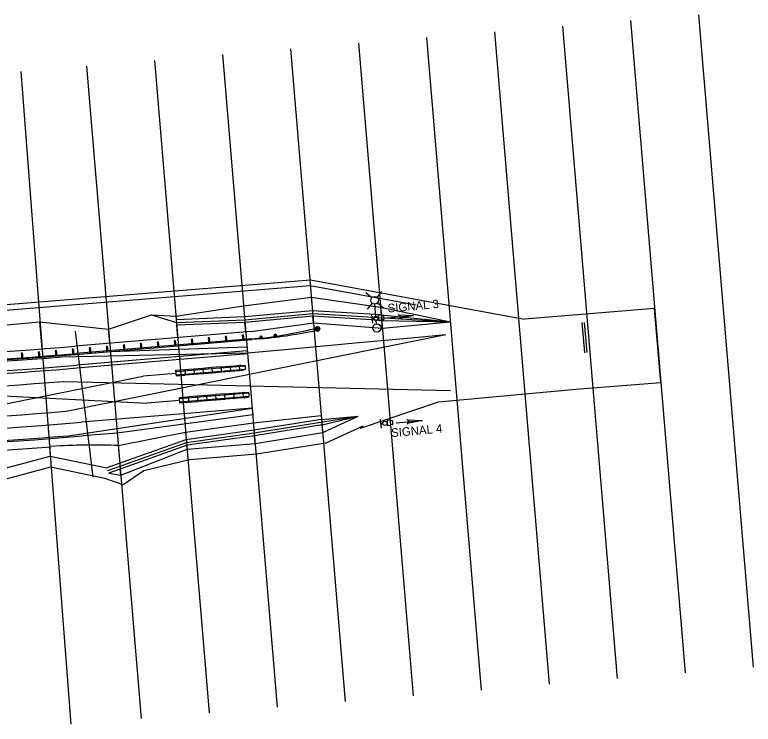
# Model space of a CAD drawing. Extents: x 223098 to 226975, y 386666 to 387582.
# Drawn here: x 223996.7 to 224267.2, y 387146.4 to 387406.5 of the extents above; entities that cross this region are included whole.
import ezdxf

# ---------------------------------------------------------------- set-up
doc = ezdxf.new("R2010")
doc.units = 0
for name, color, linetype in [('BD_X_Building', 7, 'Continuous'), ('Default', 7, 'Continuous'), ('DR_X_Erosion_Control', 7, 'Continuous'), ('DR_X_Headwall', 7, 'Continuous'), ('PF_X_Ground_Line', 7, 'Continuous'), ('PV_X_Driveway', 7, 'Continuous'), ('PV_X_EOP', 7, 'Continuous'), ('RW_X_CL_100_Distances', 7, 'Continuous'), ('RW_X_CL_100_Stations', 7, 'Continuous'), ('SV_X_Toe_of_Slope', 7, 'Continuous'), ('UT_X_Gas', 7, 'Continuous'), ('UT_X_Gas_Cells', 7, 'Continuous'), ('UT_X_Water_Cells', 7, 'Continuous'), ('VG_X_Cells', 7, 'Continuous')]:
    doc.layers.add(name, color=color, linetype=linetype)

msp = doc.modelspace()

# ---------------------------------------------------------------- linework, layer by layer
at = {"layer": 'BD_X_Building'}
for p, q in [((223981.08, 387297.25), (224104.98, 387307.24)), ((224104.98, 387307.24), (224143.7, 387300.16))]:
    msp.add_line(p, q, dxfattribs=at)
at = {"layer": 'Default'}
for p, q in [((224247.19, 387406.47), (224267.23, 387167.3)), ((224222.28, 387404.38), (224242.32, 387165.22)), ((224197.36, 387402.29), (224217.4, 387163.13)), ((224147.54, 387398.11), (224167.58, 387158.95)), ((224172.45, 387400.2), (224192.49, 387161.04)), ((224122.62, 387396.03), (224142.67, 387156.87)), ((224097.71, 387393.94), (224117.75, 387154.78)), ((224047.89, 387389.76), (224067.93, 387150.6)), ((224072.8, 387391.85), (224092.84, 387152.69)), ((224022.97, 387387.68), (224043.01, 387148.52)), ((223998.9, 387385.7), (224017.26, 387146.4))]:
    msp.add_line(p, q, dxfattribs=at)
at = {"layer": 'DR_X_Erosion_Control'}
for points in [[(223784.61, 387295.04), (223809.49, 387297.84), (223882.41, 387297.94), (223901.62, 387311.13), (223956.35, 387312.9), (223981.51, 387299.29), (224105.08, 387309.26), (224183.43, 387294.86)], [(224123.41, 387254.93), (224151.94, 387264.54), (224202.29, 387269.2), (224233.4, 387271.67), (224231.12, 387298.85), (224183.43, 387294.86)], [(224124.2, 387255.62), (224110.66, 387249.46), (224085.23, 387245.34), (224060.74, 387243.36)], [(224060.74, 387243.36), (224043.93, 387239.28), (224036.37, 387234.1), (224029.67, 387236.44)], [(224029.67, 387236.44), (224009.82, 387240.6), (223986.06, 387234.3), (223961.4, 387224.07)]]:
    msp.add_lwpolyline(points, dxfattribs=at)
at = {"layer": 'DR_X_Headwall'}
for points in [[(224046.84, 387296.42), (224055.94, 387293.66), (224080.94, 387294.69), (224105.84, 387296.97), (224156.27, 387293.86)], [(224030.83, 387239.41), (224059.62, 387249.72), (224084.42, 387253.17), (224122.54, 387259.27)]]:
    msp.add_lwpolyline(points, dxfattribs=at)
at = {"layer": 'PF_X_Ground_Line'}
for p, q in [((224013.89, 387281.05), (224081.96, 387282.5)), ((224014.62, 387272.08), (224156.38, 387268.68)), ((223973.16, 387267.73), (224045.07, 387264.09)), ((224056.97, 387265.76), (224082.37, 387267.89)), ((224073.72, 387267.49), (224076.71, 387267.75)), ((224076.71, 387267.75), (224076.89, 387267.59)), ((224076.89, 387267.59), (224077.04, 387267.77)), ((224077.04, 387267.77), (224080.03, 387268.02)), ((224080.03, 387268.02), (224080.21, 387267.87)), ((224080.21, 387267.87), (224080.36, 387268.05)), ((224080.21, 387267.87), (224080.35, 387266.21)), ((224080.36, 387268.05), (224080.8, 387268.09)), ((224080.8, 387268.09), (224082.31, 387267.96)), ((224057.03, 387265.09), (224045.07, 387264.09)), ((224060.1, 387266.35), (224056.94, 387266.09)), ((224056.94, 387266.09), (224057.11, 387264.1)), ((224082.48, 387266.56), (224057.08, 387264.43)), ((224060.1, 387266.35), (224060.28, 387266.2)), ((224060.28, 387266.2), (224060.43, 387266.38)), ((224060.28, 387266.2), (224060.42, 387264.54)), ((224063.42, 387266.63), (224060.43, 387266.38)), ((224063.42, 387266.63), (224063.6, 387266.48)), ((224063.6, 387266.48), (224063.75, 387266.66)), ((224063.6, 387266.48), (224063.74, 387264.82)), ((224066.74, 387266.91), (224063.75, 387266.66)), ((224066.74, 387266.91), (224066.92, 387266.76)), ((224066.91, 387264.92), (224067.06, 387265.1)), ((224066.92, 387266.76), (224067.08, 387266.94)), ((224066.92, 387266.76), (224067.06, 387265.1)), ((224067.06, 387265.1), (224067.24, 387264.94)), ((224070.06, 387267.19), (224067.08, 387266.94)), ((224070.23, 387265.2), (224067.24, 387264.94)), ((224070.06, 387267.19), (224070.24, 387267.04)), ((224070.23, 387265.2), (224070.38, 387265.38)), ((224070.24, 387267.04), (224070.4, 387267.22)), ((224070.24, 387267.04), (224070.38, 387265.38)), ((224070.38, 387265.38), (224070.56, 387265.22)), ((224073.39, 387267.47), (224070.4, 387267.22)), ((224073.55, 387265.47), (224070.56, 387265.22)), ((224073.39, 387267.47), (224073.57, 387267.31)), ((224073.55, 387265.47), (224073.71, 387265.65)), ((224073.57, 387267.31), (224073.72, 387267.49)), ((224073.57, 387267.31), (224073.71, 387265.65)), ((224073.71, 387265.65), (224073.89, 387265.5)), ((224076.87, 387265.75), (224073.89, 387265.5)), ((224076.87, 387265.75), (224077.03, 387265.93)), ((224076.89, 387267.59), (224077.03, 387265.93)), ((224077.03, 387265.93), (224077.21, 387265.78)), ((224080.2, 387266.03), (224077.21, 387265.78)), ((224080.2, 387266.03), (224080.35, 387266.21)), ((224080.35, 387266.21), (224080.53, 387266.06)), ((224080.96, 387266.09), (224080.53, 387266.06)), ((224080.96, 387266.09), (224082.44, 387266.47)), ((224060.27, 387264.36), (224057.11, 387264.1)), ((224060.27, 387264.36), (224060.42, 387264.54)), ((224060.42, 387264.54), (224060.6, 387264.39)), ((224063.59, 387264.64), (224060.6, 387264.39)), ((224063.59, 387264.64), (224063.74, 387264.82)), ((224063.74, 387264.82), (224063.92, 387264.67)), ((224066.91, 387264.92), (224063.92, 387264.67))]:
    msp.add_line(p, q, dxfattribs=at)
msp.add_lwpolyline([(224081.96, 387282.5), (224095.64, 387283.79), (224120.18, 387286.09), (224144.5, 387288.28), (224154.66, 387289.21)], dxfattribs=at)
for centre, radius, start, end in [((223874.12, 389011.68), 1736.26, 268.92281, 274.61725), ((223874.12, 389011.68), 1745.26, 268.92281, 274.61725), ((224081.27, 387267.12), 1.34, 330.6142, 38.9656)]:
    msp.add_arc(centre, radius, start, end, dxfattribs=at)
at = {"layer": 'PV_X_Driveway'}
for p, q in [((224107.52, 387291.71), (224107.7, 387290.86)), ((224083.54, 387287.67), (224019.04, 387282.26)), ((224019.06, 387281.98), (224083.56, 387287.39)), ((224061.99, 387285.86), (224061.41, 387286.82)), ((224061.49, 387285.82), (224061.9, 387286.86)), ((224068.22, 387286.38), (224067.63, 387287.34)), ((224067.72, 387286.34), (224068.13, 387287.38)), ((224074.44, 387286.9), (224073.86, 387287.86)), ((224073.95, 387286.86), (224074.36, 387287.9)), ((224080.67, 387287.43), (224080.09, 387288.38)), ((224080.17, 387287.38), (224080.59, 387288.42)), ((224086.95, 387287.67), (224083.56, 387287.39)), ((224086.93, 387287.89), (224083.68, 387287.61)), ((224030.85, 387283.25), (224030.27, 387284.21)), ((224030.35, 387283.21), (224030.76, 387284.25)), ((224037.08, 387283.77), (224036.49, 387284.73)), ((224036.58, 387283.73), (224036.99, 387284.77)), ((224043.3, 387284.29), (224042.72, 387285.25)), ((224042.81, 387284.25), (224043.22, 387285.29)), ((224049.53, 387284.82), (224048.95, 387285.77)), ((224049.03, 387284.78), (224049.45, 387285.81)), ((224055.76, 387285.34), (224055.18, 387286.29)), ((224055.26, 387285.3), (224055.68, 387286.34)), ((223999.7, 387280.75), (223999.13, 387281.71)), ((223999.2, 387280.71), (223999.63, 387281.75)), ((224005.93, 387281.21), (224005.36, 387282.17)), ((224005.43, 387281.18), (224005.86, 387282.21)), ((224012.16, 387281.7), (224011.59, 387282.66)), ((224011.66, 387281.66), (224012.08, 387282.7)), ((224018.39, 387282.21), (224017.81, 387283.16)), ((224017.89, 387282.17), (224018.31, 387283.2)), ((224024.62, 387282.73), (224024.04, 387283.68)), ((224024.12, 387282.69), (224024.54, 387283.73))]:
    msp.add_line(p, q, dxfattribs=at)
for points in [[(224108.4, 387291.06), (224107.28, 387292.08)], [(224108.36, 387291.65), (224107.88, 387292.1)], [(224092.53, 387288.85), (224091.97, 387289.36)], [(224092.51, 387289.15), (224092.27, 387289.37)], [(224107.78, 387290.5), (224106.78, 387291.41)], [(224108.17, 387290.7), (224106.95, 387291.82)], [(224087.04, 387287.9), (224086.54, 387288.35)], [(224087.24, 387288), (224086.63, 387288.56)], [(224087.35, 387288.18), (224086.79, 387288.69)], [(224087.34, 387288.48), (224087.09, 387288.7)], [(224092.22, 387288.57), (224091.72, 387289.03)], [(224092.42, 387288.67), (224091.81, 387289.23)]]:
    msp.add_lwpolyline(points, dxfattribs=at)
for points in [[(224055.62, 387287), (224055.12, 387286.96), (224055.18, 387286.29), (224055.68, 387286.34)], [(224061.85, 387287.52), (224061.35, 387287.48), (224061.41, 387286.82), (224061.9, 387286.86)], [(224061.9, 387286.86), (224061.41, 387286.82), (224061.49, 387285.82), (224061.99, 387285.86)], [(224068.08, 387288.04), (224067.58, 387288), (224067.63, 387287.34), (224068.13, 387287.38)], [(224068.13, 387287.38), (224067.63, 387287.34), (224067.72, 387286.34), (224068.22, 387286.38)], [(224074.31, 387288.57), (224073.81, 387288.52), (224073.86, 387287.86), (224074.36, 387287.9)], [(224074.36, 387287.9), (224073.86, 387287.86), (224073.95, 387286.86), (224074.44, 387286.9)], [(224080.53, 387289.09), (224080.04, 387289.05), (224080.09, 387288.38), (224080.59, 387288.42)], [(224080.59, 387288.42), (224080.09, 387288.38), (224080.17, 387287.38), (224080.67, 387287.43)], [(224024.48, 387284.39), (224023.98, 387284.35), (224024.04, 387283.68), (224024.54, 387283.73)], [(224030.71, 387284.91), (224030.21, 387284.87), (224030.27, 387284.21), (224030.76, 387284.25)], [(224030.76, 387284.25), (224030.27, 387284.21), (224030.35, 387283.21), (224030.85, 387283.25)], [(224036.94, 387285.43), (224036.44, 387285.39), (224036.49, 387284.73), (224036.99, 387284.77)], [(224036.99, 387284.77), (224036.49, 387284.73), (224036.58, 387283.73), (224037.08, 387283.77)], [(224043.16, 387285.96), (224042.67, 387285.91), (224042.72, 387285.25), (224043.22, 387285.29)], [(224043.22, 387285.29), (224042.72, 387285.25), (224042.81, 387284.25), (224043.3, 387284.29)], [(224049.39, 387286.48), (224048.89, 387286.44), (224048.95, 387285.77), (224049.45, 387285.81)], [(224049.45, 387285.81), (224048.95, 387285.77), (224049.03, 387284.78), (224049.53, 387284.82)], [(224055.68, 387286.34), (224055.18, 387286.29), (224055.26, 387285.3), (224055.76, 387285.34)], [(223999.58, 387282.41), (223999.08, 387282.38), (223999.13, 387281.71), (223999.63, 387281.75)], [(223999.63, 387281.75), (223999.13, 387281.71), (223999.2, 387280.71), (223999.7, 387280.75)], [(224005.81, 387282.88), (224005.31, 387282.84), (224005.36, 387282.17), (224005.86, 387282.21)], [(224005.86, 387282.21), (224005.36, 387282.17), (224005.43, 387281.18), (224005.93, 387281.21)], [(224012.03, 387283.36), (224011.53, 387283.32), (224011.59, 387282.66), (224012.08, 387282.7)], [(224012.08, 387282.7), (224011.59, 387282.66), (224011.66, 387281.66), (224012.16, 387281.7)], [(224018.25, 387283.87), (224017.75, 387283.83), (224017.81, 387283.16), (224018.31, 387283.2)], [(224018.31, 387283.2), (224017.81, 387283.16), (224017.89, 387282.17), (224018.39, 387282.21)], [(224024.54, 387283.73), (224024.04, 387283.68), (224024.12, 387282.69), (224024.62, 387282.73)]]:
    msp.add_lwpolyline(points, close=True, dxfattribs=at)
for centre, radius in [((224107.61, 387291.31), 0.833), ((224092.14, 387288.98), 0.417), ((224086.96, 387288.31), 0.417)]:
    msp.add_circle(centre, radius, dxfattribs=at)
for centre, radius, start, end in [((224068.52, 387444.42), 157.61, 276.7092, 284.3274), ((224062.58, 387515.48), 229.11, 276.1069, 281.3587), ((223874.12, 389011.68), 1735.48, 269.08669, 274.7899), ((223874.12, 389011.68), 1735.76, 269.08671, 274.7899)]:
    msp.add_arc(centre, radius, start, end, dxfattribs=at)
at = {"layer": 'PV_X_EOP'}
for p, q in [((224204.46, 387293.61), (224205.39, 387282.54)), ((224206.39, 387282.63), (224205.46, 387293.69))]:
    msp.add_line(p, q, dxfattribs=at)
at = {"layer": 'RW_X_CL_100_Distances'}
for p, q in [((224015.5, 387261.12), (224154.66, 387289.21)), ((224058.77, 387276.28), (224055.62, 387276.01)), ((224055.62, 387276.01), (224055.78, 387274.02)), ((224055.64, 387275.68), (224081.04, 387277.81)), ((224081.16, 387276.48), (224055.76, 387274.35)), ((224058.77, 387276.28), (224058.95, 387276.13)), ((224058.95, 387276.13), (224059.1, 387276.31)), ((224058.95, 387276.13), (224059.09, 387274.46)), ((224062.09, 387276.56), (224059.1, 387276.31)), ((224062.09, 387276.56), (224062.27, 387276.4)), ((224062.27, 387276.4), (224062.43, 387276.58)), ((224062.27, 387276.4), (224062.41, 387274.74)), ((224065.42, 387276.83), (224062.43, 387276.58)), ((224065.42, 387276.83), (224065.6, 387276.68)), ((224065.6, 387276.68), (224065.75, 387276.86)), ((224065.6, 387276.68), (224065.74, 387275.02)), ((224068.74, 387277.11), (224065.75, 387276.86)), ((224068.74, 387277.11), (224068.92, 387276.96)), ((224068.92, 387276.96), (224069.07, 387277.14)), ((224068.92, 387276.96), (224069.06, 387275.3)), ((224072.06, 387277.39), (224069.07, 387277.14)), ((224072.06, 387277.39), (224072.24, 387277.24)), ((224072.24, 387277.24), (224072.39, 387277.42)), ((224072.24, 387277.24), (224072.38, 387275.58)), ((224072.39, 387277.42), (224075.38, 387277.67)), ((224075.38, 387277.67), (224075.56, 387277.52)), ((224075.55, 387275.68), (224075.7, 387275.86)), ((224075.56, 387277.52), (224075.71, 387277.7)), ((224075.56, 387277.52), (224075.7, 387275.86)), ((224075.7, 387275.86), (224075.88, 387275.7)), ((224075.71, 387277.7), (224078.7, 387277.95)), ((224078.87, 387275.95), (224075.88, 387275.7)), ((224078.7, 387277.95), (224078.88, 387277.8)), ((224078.87, 387275.95), (224079.02, 387276.13)), ((224078.88, 387277.8), (224079.03, 387277.98)), ((224078.88, 387277.8), (224079.02, 387276.13)), ((224079.02, 387276.13), (224079.2, 387275.98)), ((224079.03, 387277.98), (224079.47, 387278.01)), ((224079.64, 387276.02), (224079.2, 387275.98)), ((224079.47, 387278.01), (224080.99, 387277.89)), ((224079.64, 387276.02), (224081.11, 387276.39)), ((223973.18, 387259.72), (224043.74, 387274.01)), ((224055.7, 387275.02), (224043.74, 387274.01)), ((224058.94, 387274.28), (224055.78, 387274.02)), ((224058.94, 387274.28), (224059.09, 387274.46)), ((224059.09, 387274.46), (224059.27, 387274.31)), ((224062.26, 387274.56), (224059.27, 387274.31)), ((224062.26, 387274.56), (224062.41, 387274.74)), ((224062.41, 387274.74), (224062.59, 387274.59)), ((224065.58, 387274.84), (224062.59, 387274.59)), ((224065.58, 387274.84), (224065.74, 387275.02)), ((224065.74, 387275.02), (224065.92, 387274.87)), ((224068.9, 387275.12), (224065.92, 387274.87)), ((224068.9, 387275.12), (224069.06, 387275.3)), ((224069.06, 387275.3), (224069.24, 387275.15)), ((224072.23, 387275.4), (224069.24, 387275.15)), ((224072.23, 387275.4), (224072.38, 387275.58)), ((224072.38, 387275.58), (224072.56, 387275.43)), ((224075.55, 387275.68), (224072.56, 387275.43)), ((224016.23, 387252.15), (224083.66, 387262.22))]:
    msp.add_line(p, q, dxfattribs=at)
for centre, radius, start, end in [((224079.95, 387277.05), 1.34, 330.6142, 38.9656), ((223874.12, 389011.68), 1756.26, 268.92281, 274.61725), ((223874.12, 389011.68), 1765.26, 268.92281, 274.61725)]:
    msp.add_arc(centre, radius, start, end, dxfattribs=at)
at = {"layer": 'RW_X_CL_100_Stations'}
for p, q in [((224127.45, 387302.68), (224125.31, 387304.49)), ((224129.42, 387302.84), (224131.23, 387304.98)), ((224127.62, 387300.71), (224125.8, 387298.57)), ((224129.01, 387295.9), (224128.63, 387300.38)), ((224129.59, 387300.87), (224131.73, 387299.06)), ((224127.82, 387293.41), (224127.52, 387296.63)), ((224127.66, 387295.14), (224128.32, 387295.2)), ((224127.68, 387294.9), (224128.34, 387294.96)), ((224129.8, 387295.34), (224130.07, 387295.36)), ((224129.8, 387295.34), (224130.07, 387295.36)), ((224129.83, 387295.1), (224130.09, 387295.12)), ((224129.83, 387295.1), (224130.09, 387295.12)), ((224131.13, 387296.31), (224129.99, 387296.21)), ((224130.17, 387294.27), (224129.99, 387296.21)), ((224131.31, 387294.38), (224131.13, 387296.31)), ((224131.64, 387296.11), (224131.16, 387296.06)), ((224133.17, 387295.37), (224142.79, 387296.24)), ((224137.12, 387296.44), (224142.79, 387296.24)), ((224142.79, 387296.24), (224137.25, 387295.04)), ((224129.24, 387293.14), (224129.14, 387294.4)), ((224131.31, 387294.38), (224130.17, 387294.27)), ((224131.77, 387294.67), (224131.29, 387294.63)), ((224131.04, 387254.95), (224130.74, 387258.18)), ((224133.03, 387256.88), (224133.29, 387256.91)), ((224133.03, 387256.88), (224133.29, 387256.91)), ((224134.35, 387257.86), (224133.21, 387257.76)), ((224133.39, 387255.82), (224133.21, 387257.76)), ((224134.53, 387255.93), (224134.35, 387257.86)), ((224134.87, 387257.66), (224134.38, 387257.61)), ((224134.87, 387257.66), (224134.38, 387257.61)), ((224136.39, 387256.92), (224146.01, 387257.79)), ((224140.35, 387257.98), (224146.01, 387257.79)), ((224146.01, 387257.79), (224140.47, 387256.58)), ((224130.88, 387256.69), (224131.54, 387256.75)), ((224130.88, 387256.69), (224131.54, 387256.75)), ((224130.9, 387256.45), (224131.56, 387256.51)), ((224130.9, 387256.45), (224131.56, 387256.51)), ((224133.05, 387256.65), (224133.31, 387256.67)), ((224133.05, 387256.65), (224133.31, 387256.67)), ((224134.53, 387255.93), (224133.39, 387255.82)), ((224135, 387256.22), (224134.51, 387256.18)), ((224135, 387256.22), (224134.51, 387256.18))]:
    msp.add_line(p, q, dxfattribs=at)
for centre, radius in [((224128.52, 387301.78), 1.4), ((224129.07, 387295.15), 0.757), ((224129.37, 387291.65), 1.5), ((224132.29, 387256.7), 0.757)]:
    msp.add_circle(centre, radius, dxfattribs=at)
for centre in [(224137.19, 387295.74), (224140.41, 387257.28)]:
    msp.add_arc(centre, 0.702, 275.1298, 95.1298, dxfattribs=at)
for centre in [(224131.71, 387295.39), (224134.93, 387256.94), (224134.93, 387256.94)]:
    msp.add_ellipse(centre, major_axis=(0.066, -0.718), ratio=0.45371, start_param=0, end_param=3.141593, dxfattribs=at)
at = {"layer": 'SV_X_Toe_of_Slope'}
for p, q in [((224105.34, 387302.96), (224105.75, 387297.97)), ((224080.51, 387299.82), (224080.86, 387295.69)), ((224130.73, 387299.26), (224130.98, 387296.3)), ((224055.75, 387295.93), (224055.86, 387294.66)), ((224106.12, 387293.6), (224105.92, 387295.96)), ((224130.97, 387296.42), (224156.27, 387293.86)), ((224006.7, 387284), (224005.94, 387293.96)), ((224056.4, 387288.12), (224056.02, 387292.66)), ((224081.32, 387290.21), (224081.02, 387293.7)), ((224131.14, 387294.41), (224156.27, 387293.86)), ((224131.37, 387291.62), (224131.14, 387294.41)), ((224083.31, 387290.38), (224018.81, 387284.97)), ((224031.49, 387286.03), (224031.06, 387291.22)), ((224108.97, 387259.58), (224109.09, 387258.13)), ((224109.09, 387258.13), (224122.54, 387259.27)), ((224109.26, 387256.13), (224122.54, 387259.27)), ((224084.11, 387256.83), (224084.34, 387254.17)), ((224109.5, 387253.32), (224109.26, 387256.13)), ((224059.31, 387253.49), (224059.54, 387250.71)), ((224084.74, 387249.31), (224084.5, 387252.17)), ((224009.46, 387248.1), (224009.72, 387244.71)), ((224034.63, 387248.57), (224035.18, 387242.03)), ((224059.83, 387247.29), (224059.71, 387248.68)), ((224031.16, 387238.47), (224035.54, 387237.67)), ((224035.54, 387237.67), (224035.35, 387239.97))]:
    msp.add_line(p, q, dxfattribs=at)
for points in [[(224055.75, 387295.93), (224080.51, 387299.82), (224105.34, 387302.96), (224130.73, 387299.26), (224156.27, 387293.86)], [(224130.97, 387296.42), (224105.82, 387297.97), (224080.87, 387295.69), (224055.9, 387294.66)], [(224031.06, 387291.22), (224046.84, 387296.42), (224055.75, 387295.93)], [(224131.14, 387294.41), (224105.85, 387295.97), (224081.01, 387293.69), (224055.98, 387292.66)], [(223981.43, 387291.68), (224005.94, 387293.96), (224031.06, 387291.22)], [(224083.31, 387290.38), (224106.12, 387293.6), (224131.37, 387291.62), (224156.27, 387293.86)], [(224034.63, 387248.57), (224059.31, 387253.49), (224084.11, 387256.83), (224108.97, 387259.58)], [(224109.09, 387258.13), (224084.27, 387254.16), (224059.38, 387250.69), (224030.49, 387240.35)], [(224035.54, 387237.67), (224059.83, 387247.29), (224084.74, 387249.31), (224109.5, 387253.32), (224122.54, 387259.27)], [(224109.26, 387256.13), (224084.57, 387252.18), (224059.86, 387248.74), (224031.16, 387238.47)], [(224034.63, 387248.57), (224033.15, 387248.62), (224031.91, 387248.66), (224030.22, 387248.7), (224028.15, 387248.73), (224026.3, 387248.74), (224024.03, 387248.74), (224021.51, 387248.71), (224019.36, 387248.66), (224018.18, 387248.62), (224016.86, 387248.57), (224016.16, 387248.54), (224014.79, 387248.48), (224013.34, 387248.41), (224010.01, 387248.15)], [(223959.87, 387227.77), (223984.77, 387238.1), (224009.72, 387244.71), (224030.49, 387240.35)]]:
    msp.add_lwpolyline(points, dxfattribs=at)
for radius, start, end in [(1732.76, 268.9748, 274.7899), (1768.76, 267.16046, 274.40616)]:
    msp.add_arc((223874.12, 389011.68), radius, start, end, dxfattribs=at)
at = {"layer": 'UT_X_Gas'}
msp.add_line((224025.45, 387236.99), (224018.95, 387290.53), dxfattribs=at)
at = {"layer": 'UT_X_Gas_Cells'}
for p, q in [((224031.74, 387283.04), (224081.78, 387284.73)), ((224081.78, 387284.73), (224081.9, 387283.23)), ((224019.06, 387281.98), (224031.74, 387283.04))]:
    msp.add_line(p, q, dxfattribs=at)
msp.add_arc((223874.12, 389011.68), 1735.76, 268.661, 274.7899, dxfattribs=at)
at = {"layer": 'UT_X_Water_Cells'}
for p, q in [((224083.65, 387262.31), (224021.15, 387257.07)), ((224083.65, 387262.31), (224083.86, 387259.81)), ((224083.86, 387259.81), (224034.25, 387253.15)), ((224034.25, 387253.15), (224021.57, 387252.09))]:
    msp.add_line(p, q, dxfattribs=at)
for radius, start in [(1760.76, 267.16046), (1765.76, 268.661)]:
    msp.add_arc((223874.12, 389011.68), radius, start, 274.7899, dxfattribs=at)
at = {"layer": 'VG_X_Cells'}
for p, q in [((224081.9, 387283.23), (224019.4, 387278)), ((224019.48, 387277), (224081.98, 387282.24)), ((224081.9, 387283.23), (224081.98, 387282.24))]:
    msp.add_line(p, q, dxfattribs=at)
for radius, start in [(1739.76, 267.16046), (1740.76, 272.75178)]:
    msp.add_arc((223874.12, 389011.68), radius, start, 274.7899, dxfattribs=at)

# ---------------------------------------------------------------- texts
at = {"layer": 'RW_X_CL_100_Stations'}
for s, p in [('SIGNAL 3', (224133.45, 387297.31)), ('SIGNAL 4', (224134.73, 387251.65))]:
    msp.add_text(s, height=3.125, rotation=5.1298, dxfattribs=at).set_placement(p)

doc.saveas('drawing.dxf')
